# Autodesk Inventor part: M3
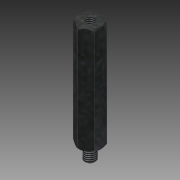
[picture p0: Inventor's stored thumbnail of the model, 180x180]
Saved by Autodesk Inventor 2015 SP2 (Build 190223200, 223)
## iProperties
Created: 2012-08
Part Number: M3
Material: Stahl
Document SubType Name: Modeling
Designer: rYan
Mass: 7.30406 g
Surface Area: 7.68922 cm^2
Volume: 0.930453 cm^3
Density: 7.85 g/cm^3
Appearance: Platte
Author: rYan
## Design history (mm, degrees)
derived "Abstandsbolzen Typ B.ipt"
feature "Volumenkörper1::Abstandsbolzen Typ B.ipt"
tag "Bezeichnung1"
node "Volumenkörper1"
other parameters: "SW" = 6, "d2" = 0, "l_" = 6.5, "d9" = 118 deg, "GA_" = 3, "A_" = 4, "d13" = 0, "d17" = 0.25, "d20" = 45 deg
